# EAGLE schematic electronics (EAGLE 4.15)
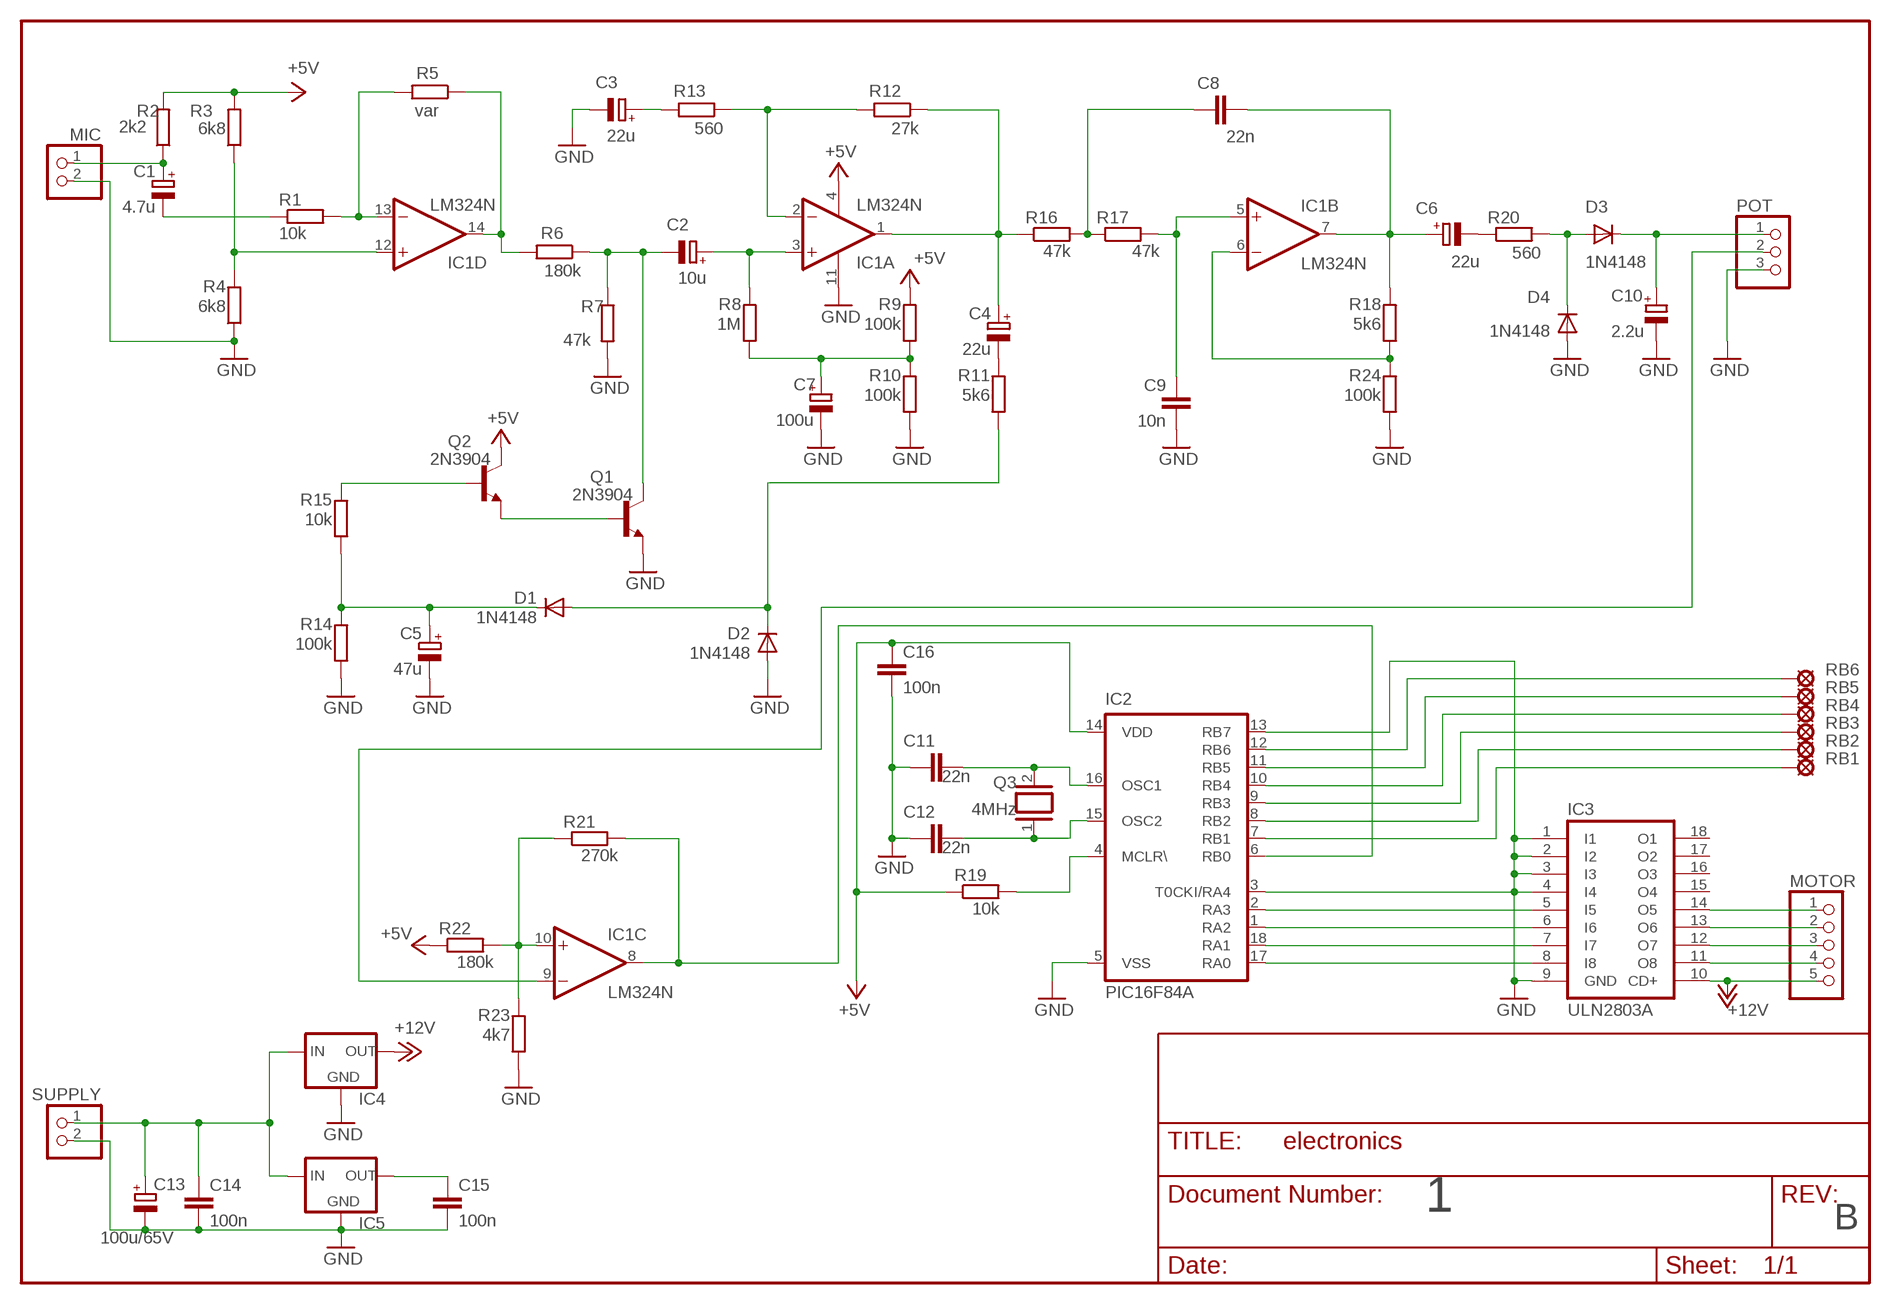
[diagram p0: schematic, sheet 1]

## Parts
C1  4.7u  CPOL-EUE2.5-5  [E2,5-5]
C2  10u  CPOL-EUE2.5-5  [E2,5-5]
C3  22u  CPOL-EUE2.5-5  [E2,5-5]
C4  22u  CPOL-EUE2.5-5  [E2,5-5]
C5  47u  CPOL-EUE2.5-5  [E2,5-5]
C6  22u  CPOL-EUE2.5-5  [E2,5-5]
C7  100u  CPOL-EUE2.5-5  [E2,5-5]
C8  22n  C-EU025-025X050  [C025-025X050]
C9  10n  C-EU025-025X050  [C025-025X050]
C10  2.2u  CPOL-EUE2.5-5  [E2,5-5]
C11  22n  C-EU025-025X050  [C025-025X050]
C12  22n  C-EU025-025X050  [C025-025X050]
C13  100u/65V  CPOL-EUE3.5-8  [E3,5-8]
C14  100n  C-EU025-025X050  [C025-025X050]
C15  100n  C-EU025-025X050  [C025-025X050]
C16  100n  C-EU025-025X050  [C025-025X050]
D1  1N4148  [DO35-10]
D2  1N4148  [DO35-10]
D3  1N4148  [DO35-10]
D4  1N4148  [DO35-10]
IC1  LM324N  [DIL14]
IC2  PIC16F84A  PIC16F84AP  [DIL18]
IC3  ULN2803A  [DIL18]
IC4  78XXL  [78XXL]
IC5  78XXL  [78XXL]
MIC  PINHD-1X2  [1X02]
MOTOR  PINHD-1X5  [1X05]
POT  PINHD-1X3  [1X03]
Q1  2N3904  [TO92]
Q2  2N3904  [TO92]
Q3  4MHz  XTAL/S  [QS]
R1  10k  R-EU_0309/10  [0309/10]
R2  2k2  R-EU_0309/10  [0309/10]
R3  6k8  R-EU_0309/10  [0309/10]
R4  6k8  R-EU_0309/10  [0309/10]
R5  var  R-EU_0309/10  [0309/10]
R6  180k  R-EU_0309/10  [0309/10]
R7  47k  R-EU_0309/10  [0309/10]
R8  1M  R-EU_0309/10  [0309/10]
R9  100k  R-EU_0309/10  [0309/10]
R10  100k  R-EU_0309/10  [0309/10]
R11  5k6  R-EU_0309/10  [0309/10]
R12  27k  R-EU_0309/10  [0309/10]
R13  560  R-EU_0309/10  [0309/10]
R14  100k  R-EU_0309/10  [0309/10]
R15  10k  R-EU_0309/10  [0309/10]
R16  47k  R-EU_0309/10  [0309/10]
R17  47k  R-EU_0309/10  [0309/10]
R18  5k6  R-EU_0309/10  [0309/10]
R19  10k  R-EU_0309/10  [0309/10]
R20  560  R-EU_0309/10  [0309/10]
R21  270k  R-EU_0309/10  [0309/10]
R22  180k  R-EU_0309/10  [0309/10]
R23  4k7  R-EU_0309/10  [0309/10]
R24  100k  R-EU_0309/10  [0309/10]
RB1  LSP10  [LSP10]
RB2  LSP10  [LSP10]
RB3  LSP10  [LSP10]
RB4  LSP10  [LSP10]
RB5  LSP10  [LSP10]
RB6  LSP10  [LSP10]
SUPPLY  PINHD-1X2  [1X02]

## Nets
+5V: C15.1 C16.1 IC1.4(P:V+) IC2.14(VDD) IC5.OUT Q2.1(C) R2.2 R3.2 R9.2 R19.1 R22.1
+12V: IC3.10(CD+) IC4.OUT MOTOR.5
GND: C3.- C5.- C7.- C9.1 C10.- C11.1 C12.1 C13.- C14.2 C15.2 C16.2 D2.A D4.A IC1.11(P:V-) IC2.3(T0CKI/RA4) IC2.5(VSS) IC2.13(RB7) IC3.1(I1) IC3.2(I2) IC3.3(I3) IC3.4(I4) IC3.9(GND) IC4.GND IC5.GND MIC.2 POT.3 Q1.3(E) R4.1 R7.2 R10.1 R14.1 R23.1 R24.1 SUPPLY.2
N$1: C1.+ MIC.1 R2.1
N$2: C7.+ R8.1 R9.1 R10.2
N$3: C3.+ R13.2
N$4: C4.- R11.2
N$5: C8.1 R16.2 R17.1
N$6: IC1.6(B:-IN) R18.1 R24.2
N$7: C1.- R1.1
N$8: IC1.13(D:-IN) R1.2 R5.2
N$9: C4.+ IC1.1(A:OUT) R12.1 R16.1
N$10: IC1.12(D:+IN) R3.1 R4.2
N$11: IC1.14(D:OUT) R5.1 R6.2
N$12: C2.- Q1.1(C) R6.1 R7.1
N$13: C2.+ IC1.3(A:+IN) R8.2
N$14: C9.2 IC1.5(B:+IN) R17.2
N$15: IC1.2(A:-IN) R12.2 R13.1
N$16: D1.A D2.C R11.1
N$17: C5.+ D1.C R14.2 R15.1
N$18: Q2.2(B) R15.2
N$19: C6.+ C8.2 IC1.7(B:OUT) R18.2
N$20: Q1.2(B) Q2.3(E)
N$21: C6.- R20.1
N$22: D3.A D4.C R20.2
N$23: C10.+ D3.C POT.1
N$24: IC1.9(C:-IN) POT.2
N$25: IC1.10(C:+IN) R21.1 R22.2 R23.2
N$26: IC1.8(C:OUT) IC2.6(RB0) R21.2
N$27: IC2.7(RB1) RB1.MP
N$28: IC2.8(RB2) RB2.MP
N$29: IC2.9(RB3) RB3.MP
N$30: IC2.10(RB4) RB4.MP
N$31: IC2.11(RB5) RB5.MP
N$32: IC2.12(RB6) RB6.MP
N$34: IC2.2(RA3) IC3.5(I5)
N$35: IC2.1(RA2) IC3.6(I6)
N$36: IC2.18(RA1) IC3.7(I7)
N$37: IC2.17(RA0) IC3.8(I8)
N$38: IC3.11(O8) MOTOR.4
N$39: IC3.12(O7) MOTOR.3
N$40: IC3.13(O6) MOTOR.2
N$41: IC3.14(O5) MOTOR.1
N$42: C11.2 IC2.16(OSC1) Q3.2
N$43: C12.2 IC2.15(OSC2) Q3.1
N$45: IC2.4(MCLR\) R19.2
N$46: C13.+ C14.1 IC4.IN IC5.IN SUPPLY.1
Unconnected: IC3.15(O4) IC3.16(O3) IC3.17(O2) IC3.18(O1)

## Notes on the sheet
- 1
- B

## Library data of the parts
C1-C7 C10 C13 = rcl:CPOL-EU: POLARIZED CAPACITOR, European symbol
C8 C9 C11 C12 C14-C16 = rcl:C-EU: CAPACITOR, European symbol
D1-D4 = diode:1N4148: DIODE
IC1 = linear:LM324: OP AMP
IC2 = microchip-2:PIC16F8*: MICROCONTROLLER 8-Bit PIC16F8X Family - CMOS Flash/EEPROM Pin Compatible : PIC16F83, PIC16CR83, PIC16F84A, PIC16CR84 see also PIC16C*
IC3 = uln-udn:ULN2803A: DRIVER ARRAY
IC4 IC5 = v-reg:78XXL: VOLTAGE REGULATOR
MIC SUPPLY = pinhead:PINHD-1X2: PIN HEADER
MOTOR = pinhead:PINHD-1X5: PIN HEADER
POT = pinhead:PINHD-1X3: PIN HEADER
Q1 Q2 = transistor-npn:2N3904: NPN Transistor
Q3 = special:XTAL/S: CRYSTAL
R1-R24 = rcl:R-EU_: RESISTOR, European symbol
RB1-RB6 = solpad:LSP10: SOLDER PAD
